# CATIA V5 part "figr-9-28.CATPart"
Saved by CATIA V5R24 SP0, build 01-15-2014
Part number: Part1
Bounding box of the stored display mesh (mm): x -75 to 75, y -50 to 50, z 0 to 40
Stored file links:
  D:\KAVITA\CATIA V5-6R2014 Project_ Kavita\CATIA V5-6R2014_partfiles\Partfiles\c09_catia_v5-6r2014_prt\figr-9-28.CATPart
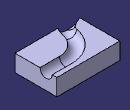
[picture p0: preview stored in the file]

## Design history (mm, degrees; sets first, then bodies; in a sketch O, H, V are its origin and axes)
Body1 (main body)
  Sketch1 on xy-plane, origin (0, 0, 0), H (1, 0, 0), V (0, 1, 0)
    line L1 (-75, 50) -> (75, 50)
    line L2 (75, 50) -> (75, -50)
    line L3 (75, -50) -> (-75, -50)
    line L4 (-75, -50) -> (-75, 50)
    axis line L5 (75, -50) -> (-75, 50)
    length L2 = 100
    length L3 = 150
    horizontal: L1 H, L3 H
    vertical: L2 V, L4 V
    midpoint: O L5
  Pad1: profile Sketch1, direction (0, 0, 1), length 40
  Sketch2 on face of Pad1, origin (75, 0, 0), H (0, 1, 0), V (0, 0, 1)
    arc A1 centre (24.1478, 40) radius 14.6047 from (9.543, 40) to (38.7525, 40) ccw
    point P1 (24.1478, 40)
    reference projected point E1 (24.1478, 40) from vertex of Sketch3
    line L1 (9.543, 40) -> (38.7525, 40)
    coincidence: P1 E1
    horizontal: L1 H
  Sketch3 on face of Pad1, origin (0, 0, 40), H (1, 0, 0), V (0, 1, 0)
    point P1 (75, 24.1478)
    line L1 (75, 24.1478) -> (28.6577, 24.1478)
    arc A1 centre (28.6577, -39.2062) radius 63.354 from (28.6577, 24.1478) to (-33.8383, -28.8149) ccw
    arc A2 centre (-62.192, -24.1005) radius 28.7429 from (-33.8383, -28.8149) to (-49.7271, -50) cw
    point P6 (-49.7271, -50)
    reference projected line E1 (75, -50) -> (75, 50) from edge [face of Pad1 | face of Pad1]
    reference projected line E2 (-75, -50) -> (75, -50) from edge [face of Pad1 | face of Pad1]
    horizontal: L1 H
    tangency: A1 L1, A2 A1
    coincidence: P1 E1, P6 E2
  Slot1: profile Sketch2, centre curve Sketch3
